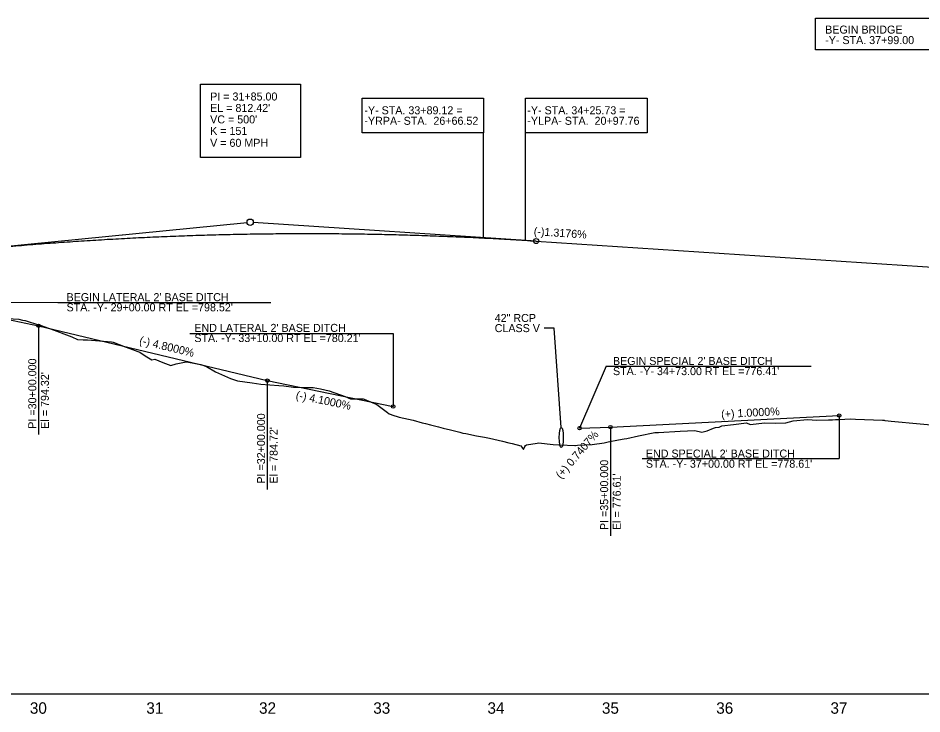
# Model space of a CAD drawing. Extents: x 579185 to 595036, y -53221 to -44640.
# Drawn here: x 581308 to 582099, y -47238 to -46630 of the extents above; entities that cross this region are included whole.
import ezdxf

# ---------------------------------------------------------------- set-up
doc = ezdxf.new("R2010")
doc.units = 0
for name, color, linetype in [('Exist Profile Cell', 7, 'Continuous'), ('Exist Vertical Profile Ground Line', 7, 'Continuous'), ('Exist Vertical Profile Horizontal Axis Label Major', 7, 'Continuous'), ('Prop Grid Mask', 7, 'Continuous'), ('Prop PFL Cross Pipe CELL', 7, 'Continuous'), ('Prop Vertical Profile Curve Label', 7, 'Continuous'), ('Prop Vertical Profile Ditch Grade Right', 7, 'Continuous'), ('Prop Vertical Profile Ditch Grade Right Label', 7, 'Continuous'), ('Prop Vertical Profile Grade', 7, 'Continuous'), ('Prop Vertical Profile Grade Label', 7, 'Continuous'), ('Prop VPI Ditch Grade Right Label', 7, 'Continuous'), ('Prop VPI Label', 7, 'Continuous')]:
    doc.layers.add(name, color=color, linetype=linetype)

msp = doc.modelspace()

# ---------------------------------------------------------------- linework, layer by layer
at = {"layer": 'Exist Profile Cell'}
msp.add_line((579326.24, -47220.55), (584953.7, -47220.55), dxfattribs=at)
at = {"layer": 'Exist Vertical Profile Ground Line'}
for points in [[(581299.01, -46892.71), (581308.85, -46893.19)], [(581308.85, -46893.19), (581312.28, -46894.23), (581314.08, -46894.45), (581314.65, -46894.51), (581327.19, -46898.47), (581328.42, -46898.87), (581330.84, -46899.71), (581339.94, -46902.82), (581350.53, -46906.85), (581355.32, -46908.75), (581360.38, -46910.91), (581365.18, -46911.18), (581368.88, -46911.41), (581372.42, -46911.56), (581383.08, -46912.52), (581389.87, -46913.03), (581391.42, -46913.32), (581401.86, -46917.43), (581406.08, -46918.78), (581413.01, -46921.37), (581414.64, -46922.15), (581419.41, -46925.28), (581425.19, -46928.8), (581427.81, -46928.14), (581434.84, -46931.01), (581441.81, -46933.76), (581446.45, -46932.33), (581455.26, -46930.55), (581457.29, -46930.88), (581468.05, -46932.83), (581473.02, -46934.53), (581480.88, -46939.1), (581493.92, -46945.03), (581500.18, -46946.98), (581513.05, -46948.85), (581520.47, -46949.96), (581536.21, -46951.09), (581540.78, -46951.56), (581549.24, -46952.63), (581558.18, -46953.04), (581566.18, -46953.06), (581572.78, -46954), (581580.43, -46955.95), (581594.35, -46960.76), (581598.97, -46962.97), (581608.23, -46962.93), (581610.09, -46962.86), (581611.05, -46963.21), (581621.91, -46967.65), (581631.28, -46974.87), (581632.71, -46975.87), (581636.78, -46977.34), (581639.9, -46978.34), (581641.39, -46978.72), (581653.87, -46981.46), (581661.66, -46983.7), (581664.58, -46984.47), (581668.99, -46985.59), (581675.76, -46987.33), (581680.01, -46988.33), (581686.43, -46989.81), (581694.55, -46992.05), (581697.11, -46992.71), (581699.74, -46993.23), (581709.02, -46995.09), (581716.18, -46996.3), (581720.47, -46997.14), (581731.81, -46999.86), (581737.42, -47001.2), (581740.16, -47001.82), (581748, -47003.8), (581748.82, -47005.03), (581750.12, -47007.08), (581751.43, -47004.61), (581751.95, -47003.68), (581752.72, -47003.12), (581762.05, -47001.69), (581763.45, -47001.42), (581776.04, -47002.62), (581781.18, -47003.13), (581781.66, -47003.16), (581782, -47003.15), (581795.22, -47003.66), (581795.74, -47003.62), (581797.42, -47003.39), (581810.23, -47002.65), (581820.73, -47001.18), (581824.3, -47000.4), (581833.18, -46998.77), (581838.35, -46997.77), (581840.67, -46997.52), (581850.8, -46995.23), (581865.18, -46992.32), (581868.24, -46992.19), (581887.11, -46991.12), (581900.13, -46990.46), (581906.2, -46992.1), (581910.79, -46990.87), (581916.25, -46988.61), (581918.05, -46987.9), (581921.32, -46987.5)], [(581921.32, -46987.5), (581923.61, -46986.41), (581933.75, -46985.32), (581945.07, -46983.93), (581948.45, -46985.13), (581961.14, -46983.87), (581970.16, -46984.1), (581979.69, -46983.91), (581986.08, -46982.15), (581998.64, -46980.85), (582006.68, -46981.43), (582016.88, -46981.27), (582020.31, -46981.23), (582022.94, -46981.02), (582026.2, -46980.79), (582036.12, -46980.28), (582040.38, -46980.58), (582064.09, -46981.53), (582065.46, -46981.6), (582066.13, -46981.7), (582066.51, -46981.7), (582071.79, -46982.25), (582122.27, -46986.97)]]:
    msp.add_lwpolyline(points, dxfattribs=at)
at = {"layer": 'Prop Grid Mask'}
for points in [[(582005.41, -46630.1), (582106.24, -46630.1), (582106.24, -46657.85), (582005.41, -46657.85)], [(581467.85, -46687.8), (581555.21, -46687.8), (581555.21, -46751.98), (581467.85, -46751.98)], [(581609.04, -46700.19), (581715.36, -46700.19), (581715.36, -46730.38), (581609.04, -46730.38)], [(581751.97, -46700.19), (581858.29, -46700.19), (581858.29, -46730.38), (581751.97, -46730.38)]]:
    msp.add_lwpolyline(points, close=True, dxfattribs=at)
at = {"layer": 'Prop PFL Cross Pipe CELL'}
msp.add_ellipse((581783.24, -46996.65), major_axis=(0, 8.75), ratio=0.2, dxfattribs=at)
at = {"layer": 'Prop Vertical Profile Curve Label'}
for p, q in [((581715.36, -46822), (581715.36, -46730.38)), ((581751.97, -46824.33), (581751.97, -46730.38))]:
    msp.add_line(p, q, dxfattribs=at)
msp.add_circle((581761.24, -46824.94), 2.25, dxfattribs=at)
at = {"layer": 'Prop Vertical Profile Ditch Grade Right'}
for points in [[(581226.24, -46877.95), (581326.24, -46898.95), (581526.24, -46946.95), (581636.24, -46969.5)], [(581799.24, -46988.5), (581826.24, -46987.5), (582026.24, -46977.5)]]:
    msp.add_lwpolyline(points, dxfattribs=at)
at = {"layer": 'Prop Vertical Profile Ditch Grade Right Label'}
for p, q in [((581226.24, -46877.95), (581343.07, -46878.75)), ((581343.07, -46878.75), (581529.3, -46878.75)), ((581326.24, -46898.95), (581326.15, -46994.02)), ((581458.36, -46905.7), (581636.29, -46905.7)), ((581636.29, -46905.7), (581636.24, -46969.5)), ((581776.96, -46900.99), (581768.15, -46900.99)), ((581783.24, -46987.9), (581776.96, -46900.99)), ((581822.58, -46934.39), (581799.24, -46988.5)), ((581822.58, -46934.39), (582001.62, -46934.39)), ((581526.24, -46946.95), (581526.15, -47042.02)), ((582026.24, -46977.5), (582026.2, -47015.01)), ((581826.24, -46987.5), (581826.15, -47082.57)), ((581853.93, -47015.01), (582026.2, -47015.01))]:
    msp.add_line(p, q, dxfattribs=at)
at = {"layer": 'Prop Vertical Profile Grade'}
msp.add_line((581761.24, -46824.94), (583296.24, -46926.07), dxfattribs=at)
msp.add_spline([(581261.24, -46833.26), (581271.24, -46832.28), (581281.24, -46831.34), (581291.24, -46830.43), (581301.24, -46829.56), (581311.24, -46828.71), (581321.24, -46827.9), (581331.24, -46827.13), (581341.24, -46826.38), (581351.24, -46825.67), (581361.24, -46824.99), (581371.24, -46824.35), (581381.24, -46823.74), (581391.24, -46823.16), (581401.24, -46822.61), (581411.24, -46822.1), (581421.24, -46821.62), (581431.24, -46821.17), (581441.24, -46820.76), (581451.24, -46820.38), (581461.24, -46820.03), (581471.24, -46819.71), (581481.24, -46819.43), (581491.24, -46819.18), (581501.24, -46818.97), (581511.24, -46818.78), (581521.24, -46818.63), (581531.24, -46818.52), (581541.24, -46818.43), (581551.24, -46818.38), (581561.24, -46818.36), (581571.24, -46818.38), (581581.24, -46818.43), (581591.24, -46818.51), (581601.24, -46818.62), (581611.24, -46818.77), (581621.24, -46818.95), (581631.24, -46819.16), (581641.24, -46819.41), (581651.24, -46819.69), (581661.24, -46820), (581671.24, -46820.35), (581681.24, -46820.73), (581691.24, -46821.14), (581701.24, -46821.58), (581711.24, -46822.06), (581721.24, -46822.57), (581731.24, -46823.11), (581741.24, -46823.69), (581751.24, -46824.3), (581761.24, -46824.94)], degree=3, dxfattribs=at)
at = {"layer": 'Prop VPI Ditch Grade Right Label'}
for centre in [(581326.24, -46898.95), (581526.24, -46946.95), (581636.24, -46969.5), (582026.24, -46977.5), (581799.24, -46988.5), (581826.24, -46987.5)]:
    msp.add_circle(centre, 1.5, dxfattribs=at)
at = {"layer": 'Prop VPI Label'}
for p, q in [((581261.24, -46833.26), (581508.5, -46808.74)), ((581761.24, -46824.94), (581513.98, -46808.65))]:
    msp.add_line(p, q, dxfattribs=at)
msp.add_circle((581511.24, -46808.47), 2.75, dxfattribs=at)

# ---------------------------------------------------------------- texts
at = {"layer": 'Exist Vertical Profile Horizontal Axis Label Major'}
for s, p in [('30', (581318.62, -47238.05)), ('31', (581420.46, -47238.05)), ('32', (581519.01, -47238.05)), ('33', (581618.85, -47238.05)), ('34', (581718.69, -47238.05)), ('35', (581818.78, -47238.05)), ('36', (581918.72, -47238.05)), ('37', (582018.58, -47238.05))]:
    msp.add_text(s, height=10, dxfattribs=at).set_placement(p)
at = {"layer": 'Prop Vertical Profile Curve Label'}
for s, p in [("VC = 500'", (581476.24, -46722.13)), ('K = 151', (581476.24, -46732.16)), ('V = 60 MPH', (581476.24, -46742.6))]:
    msp.add_text(s, height=7, dxfattribs=at).set_placement(p)
at = {"layer": 'Prop Vertical Profile Ditch Grade Right'}
for s, p in [("BEGIN LATERAL 2' BASE DITCH", (581350.71, -46877.49)), ("STA. -Y- 29+00.00 RT EL =798.52'", (581350.71, -46886.36)), ("END LATERAL 2' BASE DITCH", (581462.42, -46904.34)), ("STA. -Y- 33+10.00 RT EL =780.21'", (581462.42, -46913.21)), ("BEGIN SPECIAL 2' BASE DITCH", (581828.43, -46933.25)), ("STA. -Y- 34+73.00 RT EL =776.41'", (581828.43, -46942.12)), ("END SPECIAL 2' BASE DITCH", (581857.22, -47014.18)), ("STA. -Y- 37+00.00 RT EL =778.61'", (581857.22, -47023.06))]:
    msp.add_text(s, height=7, dxfattribs=at).set_placement(p)
for s, rotation, p in [('(-) 4.8000%', 346.50427, (581413.82, -46914.85)), ('PI =30+00.000', 90, (581324.24, -46988.95)), ("El = 794.32'", 90, (581335.24, -46988.95)), ('(-) 4.1000%', 348.41487, (581550.72, -46962.69)), ('(+) 1.0000%', 2.86241, (581923.18, -46979.68)), ('PI =32+00.000', 90, (581524.24, -47036.95)), ("El = 784.72'", 90, (581535.24, -47036.95)), ('(+) 0.7407%', 49.42551, (581783.03, -47033.27)), ('PI =35+00.000', 90, (581824.24, -47077.5)), ("El = 776.61'", 90, (581835.24, -47077.5))]:
    msp.add_text(s, height=7, rotation=rotation, dxfattribs=at).set_placement(p)
at = {"layer": 'Prop Vertical Profile Ditch Grade Right Label'}
for s, p in [('42" RCP', (581725.03, -46895.67)), ('CLASS V', (581725.03, -46904.54))]:
    msp.add_text(s, height=7, dxfattribs=at).set_placement(p)
at = {"layer": 'Prop Vertical Profile Grade Label'}
msp.add_text('(-)1.3176%', height=7, rotation=356.23077, dxfattribs=at).set_placement((581759.03, -46819.78))
at = {"layer": 'Prop VPI Label'}
for s, p in [('BEGIN BRIDGE ', (582013.97, -46643.66)), ('-Y- STA. 37+99.00', (582013.97, -46652.83)), ('PI = 31+85.00', (581476.24, -46702.13)), ("EL = 812.42'", (581476.24, -46712.13)), ('-Y- STA. 33+89.12 =', (581611.09, -46714.17)), ('-Y- STA. 34+25.73 =', (581753.56, -46714.17)), ('-YRPA- STA.  26+66.52', (581611.09, -46723.35)), ('-YLPA- STA.  20+97.76', (581753.56, -46723.35))]:
    msp.add_text(s, height=7, dxfattribs=at).set_placement(p)

doc.saveas('drawing.dxf')
